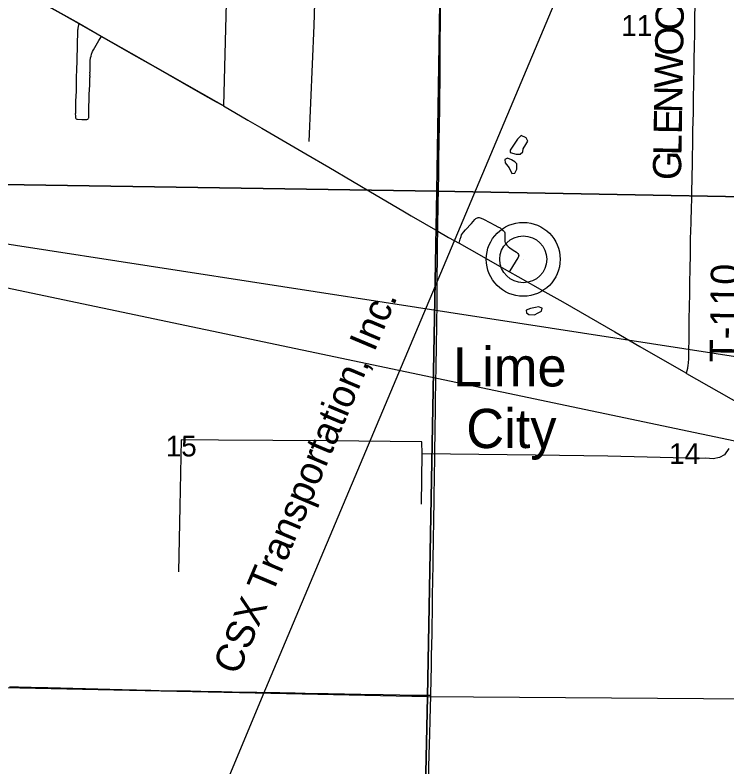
# Model space of a CAD drawing. Extents: x 0 to 34, y 0 to 22.
# Drawn here: x 5.608 to 7.043, y 14.756 to 16.271 of the extents above; entities that cross this region are included whole.
import ezdxf

# ---------------------------------------------------------------- set-up
doc = ezdxf.new("R2010")
doc.units = 0
for name, color, linetype in [('GM_X_Corporation', 7, 'Continuous'), ('GM_X_County_Road', 7, 'Continuous'), ('GM_X_Minor_Lake', 7, 'Continuous'), ('GM_X_Minor_River', 7, 'Continuous'), ('GM_X_Rail_Line', 7, 'Continuous'), ('GM_X_Rail_Line_Text', 7, 'Continuous'), ('GM_X_Section_Text', 7, 'Continuous'), ('GM_X_Township_Road', 7, 'Continuous'), ('GM_X_Township_Road_Text', 7, 'Continuous'), ('GM_X_Unincorporated', 7, 'Continuous'), ('GM_X_Unincorporated_Location', 7, 'Continuous'), ('GM_X_Unincorporated_Text', 7, 'Continuous'), ('GM_X_US_Route', 7, 'Continuous'), ('SH_Text', 7, 'Continuous')]:
    doc.layers.add(name, color=color, linetype=linetype)

msp = doc.modelspace()

# ---------------------------------------------------------------- linework, layer by layer
at = {"layer": 'GM_X_Corporation'}
for points in [[(5.4784, 16.9512), (6.4745, 16.9262), (6.4581, 15.916), (5.4509, 15.9313)], [(6.4745, 16.9262), (7.4991, 16.9078), (7.4758, 15.8976), (6.4581, 15.916)], [(5.4509, 15.9313), (6.4581, 15.916), (6.4397, 14.8975), (5.428, 14.9189)], [(6.4581, 15.916), (7.4758, 15.8976), (7.4587, 14.8897), (6.4397, 14.8975)], [(5.4122, 14.1), (6.4222, 14.1), (6.4397, 14.8975), (5.428, 14.9189)], [(6.4222, 14.1), (7.4432, 14.1), (7.4587, 14.8897), (6.4397, 14.8975)]]:
    msp.add_lwpolyline(points, close=True, dxfattribs=at)
msp.add_lwpolyline([(5.634, 16.3123), (5.7366, 16.2544), (5.7821, 16.2285), (5.8423, 16.1941), (5.891, 16.1664), (6.0135, 16.0965), (6.0291, 16.0882), (6.0415, 16.5807)], dxfattribs=at)
at = {"layer": 'GM_X_County_Road'}
for points in [[(6.4599, 15.8357), (6.4601, 15.8458), (6.4611, 15.889), (6.4616, 15.9206), (6.4623, 15.9482), (6.4625, 15.9792), (6.463, 16.0165), (6.4639, 16.0817), (6.4646, 16.1624), (6.4648, 16.2057), (6.4658, 16.2689), (6.4663, 16.3019), (6.4667, 16.336), (6.4669, 16.3609), (6.4675, 16.4012), (6.4677, 16.4261), (6.468, 16.4554)], [(6.4462, 14.9003), (6.4463, 14.903), (6.4467, 14.9316), (6.4472, 14.9589), (6.4476, 14.9801), (6.4485, 15.0242), (6.4495, 15.0863), (6.4497, 15.1013), (6.4506, 15.1634), (6.4508, 15.1752), (6.4513, 15.2112), (6.4521, 15.2554), (6.4527, 15.2908), (6.4536, 15.3511), (6.4539, 15.3685), (6.4541, 15.3897), (6.4554, 15.4773), (6.4557, 15.4966), (6.4566, 15.5637), (6.4572, 15.6029), (6.4586, 15.6916), (6.4589, 15.7431), (6.4595, 15.781), (6.4597, 15.8101), (6.4599, 15.8357)], [(5.597, 14.9176), (5.615, 14.9172), (5.6405, 14.9168), (5.6567, 14.9164), (5.6747, 14.916), (5.7505, 14.9143), (5.8245, 14.9124), (5.8816, 14.9108), (5.8984, 14.9104), (5.9618, 14.9092), (6.0035, 14.9082), (6.0246, 14.9078), (6.0457, 14.9073), (6.0631, 14.9069), (6.0955, 14.9065), (6.1421, 14.9059), (6.1725, 14.9052), (6.1931, 14.9048), (6.221, 14.9042), (6.239, 14.9038), (6.3049, 14.9025), (6.3503, 14.9019), (6.3833, 14.9013), (6.4019, 14.9009), (6.4443, 14.9004), (6.4462, 14.9003)], [(6.4346, 14.409), (6.4348, 14.4157), (6.4358, 14.4449), (6.4367, 14.4847), (6.4375, 14.5158), (6.4381, 14.5406), (6.4384, 14.5624), (6.4389, 14.5823), (6.4394, 14.609), (6.4402, 14.6438), (6.4408, 14.6718), (6.4412, 14.6935), (6.442, 14.7364), (6.4423, 14.7569), (6.4432, 14.8017), (6.4438, 14.8216), (6.4448, 14.8508), (6.4462, 14.9003)]]:
    msp.add_lwpolyline(points, dxfattribs=at)
at = {"layer": 'GM_X_Minor_Lake'}
for p, q in [((6.6315, 15.9956), (6.6323, 16.0013)), ((6.6154, 15.9753), (6.6086, 15.9795)), ((6.6435, 15.6679), (6.6552, 15.667))]:
    msp.add_line(p, q, dxfattribs=at)
for points in [[(6.6323, 16.0013), (6.6374, 16.0103), (6.6416, 16.0167), (6.6383, 16.0236), (6.6278, 16.0283), (6.6209, 16.0208), (6.617, 16.0147), (6.6059, 15.9989), (6.6058, 15.994), (6.6178, 15.9908), (6.6262, 15.9907), (6.6315, 15.9956)], [(6.6086, 15.9795), (6.6007, 15.9823), (6.595, 15.9801), (6.5961, 15.9733), (6.6039, 15.9629), (6.609, 15.9518), (6.6155, 15.9525), (6.6193, 15.9601), (6.6194, 15.9661), (6.6191, 15.9714), (6.6154, 15.9753)], [(6.6552, 15.667), (6.6624, 15.6707), (6.6689, 15.6744), (6.6701, 15.6805), (6.6633, 15.6828), (6.6573, 15.6814), (6.6467, 15.6796), (6.6379, 15.6763), (6.639, 15.671), (6.6435, 15.6679)]]:
    msp.add_lwpolyline(points, dxfattribs=at)
at = {"layer": 'GM_X_Minor_River'}
for points in [[(6.4541, 16.911), (6.2264, 16.9146), (6.2245, 16.7135), (6.218, 16.498), (6.2106, 16.2498), (6.2, 16.0162)], [(6.4273, 15.2858), (6.4283, 15.3867), (6.4278, 15.4114), (6.2371, 15.413), (6.0184, 15.4143), (5.9432, 15.4148), (5.9407, 15.2809), (5.9379, 15.1489)], [(7.0465, 15.3975), (7.0376, 15.3847), (7.0277, 15.3792), (7.0152, 15.377), (7.0001, 15.378), (6.9876, 15.3774)], [(6.9876, 15.3774), (6.803, 15.3824), (6.6568, 15.3842), (6.4283, 15.3867)]]:
    msp.add_lwpolyline(points, dxfattribs=at)
at = {"layer": 'GM_X_Rail_Line'}
msp.add_lwpolyline([(5.7724, 14.1), (5.9023, 14.4065), (6.108, 14.9012), (7.0925, 17.2371), (7.3462, 17.8422), (7.5826, 18.397), (7.8741, 19.1084), (7.9022, 19.1708), (7.9338, 19.2375), (7.9584, 19.2815), (7.9927, 19.3184), (8.0524, 19.3602), (8.3458, 19.5368)], dxfattribs=at)
at = {"layer": 'GM_X_Township_Road'}
msp.add_line((5.7773, 16.2194), (5.7823, 16.228), dxfattribs=at)
for points in [[(6.9663, 15.6187), (6.9664, 15.6268), (6.9666, 15.6403), (6.9668, 15.6582), (6.9679, 15.7092), (6.968, 15.7148), (6.9681, 15.7316), (6.9685, 15.7596), (6.969, 15.7882), (6.9696, 15.8199), (6.9705, 15.8522), (6.9714, 15.8853), (6.9717, 15.8975), (6.9721, 15.9131), (6.9731, 15.9734), (6.9733, 15.9852), (6.9741, 16.0107), (6.9742, 16.0175), (6.9743, 16.038), (6.975, 16.0747), (6.9753, 16.0933), (6.9759, 16.143), (6.9764, 16.1567), (6.9768, 16.1698), (6.9768, 16.1835), (6.9772, 16.2071), (6.978, 16.2338), (6.9781, 16.2525), (6.9782, 16.2636), (6.9785, 16.2933)], [(5.7346, 16.2424), (5.7344, 16.2403), (5.7343, 16.2359), (5.7341, 16.2304), (5.7338, 16.2187), (5.7337, 16.2131), (5.7336, 16.2094), (5.7333, 16.1982), (5.7331, 16.1921), (5.7328, 16.1803), (5.732, 16.1592), (5.7318, 16.1474), (5.7314, 16.1175), (5.7303, 16.0976), (5.7299, 16.0865), (5.7299, 16.0734), (5.7297, 16.0712), (5.7299, 16.0687), (5.7299, 16.0675), (5.7299, 16.065), (5.7302, 16.0638), (5.7307, 16.0627), (5.7316, 16.0618), (5.7327, 16.0612), (5.7339, 16.061), (5.7432, 16.0604), (5.7506, 16.0603), (5.7531, 16.0606), (5.7549, 16.0612), (5.7558, 16.062), (5.7565, 16.063), (5.7568, 16.0641), (5.7571, 16.0741), (5.757, 16.0759), (5.757, 16.0777), (5.7572, 16.0839), (5.7572, 16.0876), (5.7577, 16.0988), (5.758, 16.1118), (5.7587, 16.1298), (5.7592, 16.1448), (5.7594, 16.1454), (5.7594, 16.1472), (5.7592, 16.1479), (5.7593, 16.1491), (5.7594, 16.1509), (5.7593, 16.1516), (5.7594, 16.154), (5.7593, 16.1547), (5.7593, 16.1559), (5.7594, 16.1571), (5.7594, 16.1596), (5.7595, 16.1677), (5.7596, 16.172), (5.7597, 16.1757), (5.7598, 16.1801), (5.7602, 16.1831), (5.7605, 16.1848), (5.7614, 16.1883), (5.7626, 16.1924), (5.7646, 16.1976), (5.7662, 16.201), (5.7718, 16.21), (5.7773, 16.2194)], [(5.7368, 16.2539), (5.7352, 16.2479), (5.7348, 16.2444), (5.7346, 16.2424)], [(6.5029, 15.8111), (6.5055, 15.8196), (6.5071, 15.8249), (6.5082, 15.8278), (6.5097, 15.8305), (6.5119, 15.8335), (6.516, 15.8382), (6.5279, 15.8509), (6.5347, 15.859), (6.5365, 15.8607), (6.5381, 15.8617), (6.5398, 15.8625), (6.5416, 15.8629), (6.5435, 15.863), (6.5453, 15.8627), (6.5477, 15.862), (6.5521, 15.8598), (6.5652, 15.8527), (6.5752, 15.8476), (6.5813, 15.8444), (6.5855, 15.8419), (6.5885, 15.8398), (6.592, 15.8371), (6.5933, 15.8357), (6.5943, 15.8342), (6.5949, 15.8324), (6.5953, 15.83), (6.5953, 15.8269), (6.5949, 15.8201), (6.5951, 15.8169), (6.5955, 15.8145), (6.5962, 15.8121), (6.5973, 15.8099), (6.5991, 15.8074), (6.6017, 15.8047), (6.6056, 15.8016), (6.6123, 15.7971), (6.6185, 15.793), (6.6198, 15.7921), (6.6208, 15.7912), (6.6217, 15.7902), (6.6229, 15.7886), (6.6236, 15.7867)], [(6.6044, 15.7539), (6.609, 15.7609), (6.6111, 15.764), (6.6223, 15.7816), (6.623, 15.7831), (6.6235, 15.7849), (6.6236, 15.7867)], [(6.9613, 15.5488), (6.9627, 15.5547), (6.9638, 15.5595), (6.9649, 15.5656), (6.9654, 15.5699), (6.9659, 15.5793), (6.966, 15.5881), (6.966, 15.5946), (6.9663, 15.6187)]]:
    msp.add_lwpolyline(points, dxfattribs=at)
at = {"layer": 'GM_X_Unincorporated'}
for radius in [0.0744, 0.0472]:
    msp.add_circle((6.6323, 15.7788), radius, dxfattribs=at)
at = {"layer": 'GM_X_Unincorporated_Location'}
msp.add_line((6.6323, 15.7788), (6.6323, 15.7788), dxfattribs=at)
at = {"layer": 'GM_X_US_Route'}
msp.add_line((5.7368, 16.2539), (5.7823, 16.228), dxfattribs=at)
for points in [[(5.6343, 16.3118), (5.6457, 16.3056), (5.7058, 16.2716), (5.7368, 16.2539)], [(5.7823, 16.228), (5.8425, 16.1935), (5.8913, 16.1659), (5.9452, 16.1349), (5.9907, 16.109), (6.0137, 16.0959), (6.0277, 16.0886), (6.0286, 16.0881)], [(6.0286, 16.0881), (6.0777, 16.059), (6.1057, 16.0428), (6.1943, 15.9911), (6.2406, 15.9643), (6.3359, 15.9081), (6.3897, 15.8766)], [(6.3897, 15.8766), (6.4068, 15.8666), (6.4599, 15.8357)], [(6.4599, 15.8357), (6.482, 15.8229), (6.5029, 15.8111)], [(6.5029, 15.8111), (6.5232, 15.7997), (6.6044, 15.7539)], [(6.6044, 15.7539), (6.6217, 15.7441), (6.6756, 15.7136)], [(6.6756, 15.7136), (6.7121, 15.693), (6.7467, 15.6733), (6.8171, 15.6324), (6.8671, 15.6033), (6.9597, 15.5498), (6.9613, 15.5488)], [(6.9613, 15.5488), (7.0266, 15.5116), (7.0758, 15.4836), (7.1403, 15.4473), (7.216, 15.4043), (7.323, 15.344), (7.3895, 15.3064), (7.4295, 15.2838), (7.4704, 15.2605)]]:
    msp.add_lwpolyline(points, dxfattribs=at)
at = {"layer": 'SH_Text'}
msp.add_lwpolyline([(3.9929, 16.0574), (9.3797, 15.2243), (9.3797, 14.9242)], close=True, dxfattribs=at)

# ---------------------------------------------------------------- texts
at = {"layer": 'GM_X_Rail_Line_Text'}
msp.add_text('CSX Transportation, Inc.', height=0.056629, rotation=67.1566, dxfattribs=at).set_placement((6.0577, 14.939))
at = {"layer": 'GM_X_Section_Text'}
for s, p in [('11', (6.83, 16.229)), ('15', (5.9121, 15.3817)), ('14', (6.9262, 15.3664))]:
    msp.add_text(s, height=0.04186, rotation=0, dxfattribs=at).set_placement(p)
at = {"layer": 'GM_X_Township_Road_Text'}
for s, height, rotation, p in [('O', 0.0568, 89.0297, (6.9552, 16.2389)), ('O', 0.0568, 89.0273, (6.9544, 16.1889)), ('W', 0.0568, 89.0302, (6.9533, 16.1231)), ('N', 0.0568, 89.0297, (6.9524, 16.0731)), ('E', 0.0568, 89.0271, (6.9517, 16.0306)), ('L', 0.0568, 89.0297, (6.951, 15.9881)), ('G', 0.0568, 89.0273, (6.9501, 15.9381)), ('T-110', 0.05682, 89.1704, (7.0644, 15.5709))]:
    msp.add_text(s, height=height, rotation=rotation, dxfattribs=at).set_placement(p)
at = {"layer": 'GM_X_Unincorporated_Text'}
for s, p in [('Lime', (6.4908, 15.5227)), ('City', (6.5175, 15.3985))]:
    msp.add_text(s, height=0.07898, rotation=0, dxfattribs=at).set_placement(p)

doc.saveas('drawing.dxf')
